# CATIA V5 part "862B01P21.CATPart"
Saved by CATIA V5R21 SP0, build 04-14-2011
Part number: 862B01P21
Bounding box of the stored display mesh (mm): x -76.5 to 76.5, y -25.54 to 25.54, z -6.5 to 6.5
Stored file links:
  C:\Users\ALI OZGUN\Desktop\alhan\862B01P21.CATPart
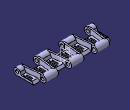
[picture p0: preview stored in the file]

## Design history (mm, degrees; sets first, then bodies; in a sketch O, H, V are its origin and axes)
Body1 (main body)
  Sketch1 on yz-plane, origin (0, 0, 0), H (0, 1, 0), V (0, 0, 1)
    construction line L1 (-19.05, 0) -> (19.05, 0)
    point P1 (-19.05, 0)
    point P2 (19.05, 0)
    line L2 (-19.05, 6.5) -> (19.05, 6.5)
    line L3 (19.05, -6.5) -> (-19.05, -6.5)
    arc A1 centre (19.05, 0) radius 6.5 from (19.05, 6.5) to (19.05, -6.5) cw
    arc A2 centre (-19.05, 0) radius 6.5 from (-19.05, -6.5) to (-19.05, 6.5) cw
    circle A3 centre (19.05, 0) radius 3.25
    circle A4 centre (-19.05, 0) radius 3.25
    distance L1 L2 = 6.5
    length L1 = 38.1
    distance P2 V = 19.05
    radius A3 = 3.25
    radius A4 = 3.25
    coincidence: P1 H
    horizontal: L1 H
    tangency: A1 L2, A2 L2, A1 L3, A2 L3
  Pad1: profile Sketch1, direction (1, 0, 0), length 76.5, mirrored extent
  Sketch2 on face of Pad1 from Sketch1.L2, origin (0, 0, 6.5), H (1, 0, 0), V (0, 1, 0)
    line L1 (38, -14) -> (64, -14)
    line L2 (64, -14) -> (64, -36.0786)
    line L3 (64, -36.0786) -> (38, -36.0786)
    line L4 (38, -36.0786) -> (38, -14)
    line L5 (-13, -14) -> (13, -14)
    line L6 (13, -14) -> (13, -36.0786)
    line L7 (13, -36.0786) -> (-13, -36.0786)
    line L8 (-13, -36.0786) -> (-13, -14)
    point P7 (13, -36.0786)
    line L9 (-64, -14) -> (-38, -14)
    line L10 (-38, -14) -> (-38, -32.269)
    line L11 (-38, -32.269) -> (-64, -32.269)
    line L12 (-64, -32.269) -> (-64, -14)
    line L13 (85.7823, 31.3847) -> (63.5, 31.3847)
    line L14 (63.5, 31.3847) -> (63.5, 14)
    line L15 (63.5, 14) -> (85.7823, 14)
    line L16 (85.7823, 14) -> (85.7823, 31.3847)
    point P17 (12.5, 31.3847)
    line L17 (12.5, 31.3847) -> (38.5, 31.3847)
    line L18 (38.5, 31.3847) -> (38.5, 14)
    line L19 (38.5, 14) -> (12.5, 14)
    line L20 (12.5, 14) -> (12.5, 31.3847)
    point P19 (38.5, 14)
    line L21 (-38.5, 32.0801) -> (-12.5, 32.0801)
    line L22 (-12.5, 32.0801) -> (-12.5, 14)
    line L23 (-12.5, 14) -> (-38.5, 14)
    line L24 (-38.5, 14) -> (-38.5, 32.0801)
    point P23 (-12.5, 14)
    line L25 (-81.4786, 33.8185) -> (-63.5, 33.8185)
    line L26 (-63.5, 33.8185) -> (-63.5, 14)
    line L27 (-63.5, 14) -> (-81.4786, 14)
    line L28 (-81.4786, 14) -> (-81.4786, 33.8185)
    point P27 (-63.5, 14)
    reference projected line E1 (76.5, 19.05) -> (76.5, -19.05) from edge [face of Pad1 from Sketch1.L2 | end face of Pad1]
    reference projected line E2 (-76.5, 19.05) -> (-76.5, -19.05) from edge [start face of Pad1 | face of Pad1 from Sketch1.L2]
    reference projected line E3 (-76.5, 19.05) -> (-76.5, -19.05) from edge [start face of Pad1 | face of Pad1 from Sketch1.L2]
    reference projected line E4 (76.5, 19.05) -> (76.5, -19.05) from edge [face of Pad1 from Sketch1.L2 | end face of Pad1]
    distance L14 E1 = 13
    distance L26 E2 = 13
    distance L12 E3 = 12.5
    distance L2 E4 = 12.5
    distance L23 L5 = 28
    distance L5 H = 14
    distance L4 L2 = 26
    distance L12 L10 = 26
    distance L10 L8 = 25
    distance L6 L4 = 25
    distance L24 L26 = 25
    distance L18 L14 = 25
    distance L26 L22 = 51
    distance L20 L18 = 26
    horizontal: L1 H, L3 H, L5 H, L7 H, L9 H, L11 H, L13 H, L15 H, L17 H, L19 H, L21 H, L23 H, L25 H, L27 H
    vertical: L2 V, L4 V, L6 V, L8 V, L10 V, L12 V, L14 V, L16 V, L18 V, L20 V, L22 V, L24 V, L26 V, L28 V
    coincidence: P7 L3, P17 L13, P19 L15, P23 L15, P27 L15, L1 L5, L9 L5
  Pocket1: profile Sketch2, direction (0, 0, -1), length 53.5
  Sketch3 on end face of Pad1, origin (76.5, 0, 0), H (0, 1, 0), V (0, 0, 1)
    projected arc E1 centre (19.05, 0) radius 6.5 from (19.05, -6.5) to (19.05, 6.5) ccw from edge [face of Pocket1 from Sketch2.L14 | face of Pad1 from Sketch1.A1]
    projected arc E2 centre (19.05, 0) radius 6.5 from (19.05, -6.5) to (13.0358, 2.4657) ccw from edge [face of Pocket1 from Sketch2.L14 | face of Pad1 from Sketch1.A1]
    point P1 (19.05, -6.5)
    projected arc E3 centre (-19.05, 0) radius 6.5 from (-19.05, 6.5) to (-19.05, -6.5) ccw from edge [face of Pad1 from Sketch1.A2 | end face of Pad1]
    projected arc E4 centre (-19.05, 0) radius 6.5 from (-13.0358, 2.4657) to (-19.05, -6.5) ccw from edge [face of Pad1 from Sketch1.A2 | end face of Pad1]
    point P4 (-19.05, -6.5)
    projected line E5 (-19.05, -6.5) -> (14, -6.5) from edge [face of Pad1 from Sketch1.L3 | end face of Pad1]
    point P5 (-19.05, -6.5)
    projected line E6 (19.05, -6.5) -> (14, -6.5) from edge [face of Pocket1 from Sketch2.L14 | face of Pad1 from Sketch1.L3]
    point P7 (19.05, -6.5)
    line L1 (-13.0358, 2.4657) -> (-11, -2.5)
    line L2 (-11, -2.5) -> (11, -2.5)
    point P10 (11, -2.5)
    line L3 (11, -2.5) -> (13.0358, 2.4657)
    distance L2 E5 = 4
    length L2 = 22
    distance P10 V = 11
    horizontal: L2 H
    tangency: L3 E1, L1 E3
    coincidence: P1 P7, P4 P5
  Pocket2: profile Sketch3, direction (-1, 0, 0), length 172.5, outer side
  Sketch4 on face of Pocket2 from Sketch3.L2, origin (0, 0, -2.5), H (1, 0, 0), V (0, 1, 0)
    projected line E1 (38, -14) -> (38, -25.55) from edge [face of Pocket2 | face of Pocket1 from Sketch2.L4]
    projected line E2 (38, -14) -> (38, -19.05) from edge [face of Pocket2 | face of Pocket1 from Sketch2.L4]
    point P1 (38, -14)
    point P2 (38, -25.55)
    projected line E3 (13, -25.55) -> (13, -14) from edge [face of Pocket2 | face of Pocket1 from Sketch2.L6]
    projected line E4 (13, -19.05) -> (13, -14) from edge [face of Pocket2 | face of Pocket1 from Sketch2.L6]
    point P3 (13, -25.55)
    point P4 (13, -14)
    projected line E5 (64, -25.55) -> (64, -14) from edge [face of Pocket2 | face of Pocket1 from Sketch2.L2]
    projected line E6 (64, -19.05) -> (64, -14) from edge [face of Pocket2 | face of Pocket1 from Sketch2.L2]
    point P5 (64, -25.55)
    point P6 (64, -14)
    projected line E7 (38.5, 14) -> (38.5, 25.55) from edge [face of Pocket2 | face of Pocket1 from Sketch2.L18]
    projected line E8 (38.5, 14) -> (38.5, 19.05) from edge [face of Pocket2 | face of Pocket1 from Sketch2.L18]
    point P7 (38.5, 14)
    point P8 (38.5, 25.55)
    projected line E9 (63.5, 14) -> (63.5, 25.55) from edge [face of Pocket1 from Sketch2.L14 | face of Pocket2]
    projected line E10 (63.5, 14) -> (63.5, 19.05) from edge [face of Pocket1 from Sketch2.L14 | face of Pocket2]
    point P9 (63.5, 14)
    point P10 (63.5, 25.55)
    projected line E11 (12.5, 25.55) -> (12.5, 14) from edge [face of Pocket2 | face of Pocket1 from Sketch2.L20]
    projected line E12 (12.5, 19.05) -> (12.5, 14) from edge [face of Pocket2 | face of Pocket1 from Sketch2.L20]
    point P11 (12.5, 25.55)
    point P12 (12.5, 14)
    offset line E13 (9.5, 25.55) -> (9.5, 14) from edge [face of Pocket2 | face of Pocket1 from Sketch2.L20]
    offset line E14 (9.5, 19.05) -> (9.5, 14) from edge [face of Pocket2 | face of Pocket1 from Sketch2.L20]
    point P13 (9.5, 25.55)
    point P14 (9.5, 14)
    offset line E15 (16, -25.55) -> (16, -14) from edge [face of Pocket2 | face of Pocket1 from Sketch2.L6]
    offset line E16 (16, -19.05) -> (16, -14) from edge [face of Pocket2 | face of Pocket1 from Sketch2.L6]
    point P15 (16, -25.55)
    point P16 (16, -14)
    offset line E17 (35, -14) -> (35, -25.55) from edge [face of Pocket2 | face of Pocket1 from Sketch2.L4]
    offset line E18 (35, -14) -> (35, -19.05) from edge [face of Pocket2 | face of Pocket1 from Sketch2.L4]
    point P17 (35, -14)
    point P18 (35, -25.55)
    offset line E19 (41.5, 14) -> (41.5, 25.55) from edge [face of Pocket2 | face of Pocket1 from Sketch2.L18]
    offset line E20 (41.5, 14) -> (41.5, 19.05) from edge [face of Pocket2 | face of Pocket1 from Sketch2.L18]
    point P19 (41.5, 14)
    point P20 (41.5, 25.55)
    offset line E21 (60.5, 14) -> (60.5, 25.55) from edge [face of Pocket1 from Sketch2.L14 | face of Pocket2]
    offset line E22 (60.5, 14) -> (60.5, 19.05) from edge [face of Pocket1 from Sketch2.L14 | face of Pocket2]
    point P21 (60.5, 14)
    point P22 (60.5, 25.55)
    offset line E23 (67, -25.55) -> (67, -14) from edge [face of Pocket2 | face of Pocket1 from Sketch2.L2]
    offset line E24 (67, -19.05) -> (67, -14) from edge [face of Pocket2 | face of Pocket1 from Sketch2.L2]
    point P23 (67, -25.55)
    point P24 (67, -14)
    line L1 (13, -14) -> (9.5, 14)
    line L2 (16, -14) -> (12.5, 14)
    line L3 (35, -14) -> (38.5, 14)
    line L4 (38, -14) -> (41.5, 14)
    line L5 (64, -14) -> (60.5, 14)
    line L6 (67, -14) -> (63.5, 14)
    projected line E25 through (0, -19.05) direction (1, 0) from axis of face of Pocket2
    projected line E26 (13, -19.05) -> (16, -19.05) from axis of face of Pocket2
    projected line E27 (64, -19.05) -> (67, -19.05) from axis of face of Pocket2
    projected line E28 (35, -19.05) -> (38, -19.05) from axis of face of Pocket2
    point P25 (-10000000, -19.05)
    point P26 (10000000, -19.05)
    point P27 (67, -19.05)
    point P28 (38, -19.05)
    point P29 (64, -19.05)
    point P30 (64, -19.05)
    point P31 (38, -19.05)
    point P32 (35, -19.05)
    point P33 (16, -19.05)
    point P34 (35, -19.05)
    point P35 (16, -19.05)
    point P36 (13, -19.05)
    point P37 (13, -19.05)
    projected line E29 through (0, 19.05) direction (1, 0) from axis of face of Pocket2
    projected line E30 (9.5, 19.05) -> (12.5, 19.05) from axis of face of Pocket2
    projected line E31 (38.5, 19.05) -> (41.5, 19.05) from axis of face of Pocket2
    projected line E32 (60.5, 19.05) -> (63.5, 19.05) from axis of face of Pocket2
    point P38 (-10000000, 19.05)
    point P39 (10000000, 19.05)
    point P40 (63.5, 19.05)
    point P41 (9.5, 19.05)
    point P42 (9.5, 19.05)
    point P43 (12.5, 19.05)
    point P44 (12.5, 19.05)
    point P45 (38.5, 19.05)
    point P46 (38.5, 19.05)
    point P47 (41.5, 19.05)
    point P48 (60.5, 19.05)
    point P49 (41.5, 19.05)
    point P50 (60.5, 19.05)
    point P51 (-10000000, -19.05)
    point P52 (10000000, -19.05)
    point P53 (-10000000, 19.05)
    point P54 (10000000, 19.05)
    construction line L7 through (0, -19.05) direction (-1, 0)
    construction line L8 through (0, 19.05) direction (-1, 0)
    point P55 (-10000000, -19.05)
    point P56 (10000000, -19.05)
    point P57 (-16, -19.05)
    point P58 (-13, -19.05)
    point P59 (-67, -19.05)
    point P60 (-64, -19.05)
    point P61 (-38, -19.05)
    point P62 (-35, -19.05)
    point P63 (-38, -25.55)
    point P64 (-38, -14)
    point P65 (-38, -19.05)
    point P66 (-13, -14)
    point P67 (-13, -25.55)
    point P68 (-13, -19.05)
    point P69 (-64, -14)
    point P70 (-64, -25.55)
    point P71 (-64, -19.05)
    point P72 (-38.5, 25.55)
    point P73 (-38.5, 14)
    point P74 (-38.5, 19.05)
    point P75 (-63.5, 25.55)
    point P76 (-63.5, 14)
    point P77 (-63.5, 19.05)
    point P78 (-12.5, 14)
    point P79 (-12.5, 25.55)
    point P80 (-12.5, 19.05)
    point P81 (-9.5, 14)
    point P82 (-9.5, 25.55)
    point P83 (-9.5, 19.05)
    point P84 (-16, -14)
    point P85 (-16, -25.55)
    point P86 (-16, -19.05)
    point P87 (-35, -25.55)
    point P88 (-35, -14)
    point P89 (-35, -19.05)
    point P90 (-41.5, 25.55)
    point P91 (-41.5, 14)
    point P92 (-41.5, 19.05)
    point P93 (-60.5, 25.55)
    point P94 (-60.5, 14)
    point P95 (-60.5, 19.05)
    point P96 (-67, -14)
    point P97 (-67, -25.55)
    line L9 (-13, -14) -> (-9.5, 14)
    line L10 (-16, -14) -> (-12.5, 14)
    line L11 (-35, -14) -> (-38.5, 14)
    line L12 (-38, -14) -> (-41.5, 14)
    line L13 (-64, -14) -> (-60.5, 14)
    line L14 (-67, -14) -> (-63.5, 14)
    point P98 (-10000000, 19.05)
    point P99 (10000000, 19.05)
    point P100 (-12.5, 19.05)
    point P101 (-9.5, 19.05)
    point P102 (-41.5, 19.05)
    point P103 (-38.5, 19.05)
    point P104 (-60.5, 19.05)
    construction line L15 through (0, -19.05) direction (-1, 0)
    line L16 (-13, -19.05) -> (-16, -19.05)
    line L17 (-64, -19.05) -> (-67, -19.05)
    line L18 (-35, -19.05) -> (-38, -19.05)
    construction line L19 (-38, -14) -> (-38, -25.55)
    line L20 (-38, -14) -> (-38, -19.05)
    construction line L21 (-13, -25.55) -> (-13, -14)
    line L22 (-13, -19.05) -> (-13, -14)
    construction line L23 (-64, -25.55) -> (-64, -14)
    line L24 (-64, -19.05) -> (-64, -14)
    construction line L25 (-38.5, 14) -> (-38.5, 25.55)
    line L26 (-38.5, 14) -> (-38.5, 19.05)
    construction line L27 (-63.5, 14) -> (-63.5, 25.55)
    line L28 (-63.5, 14) -> (-63.5, 19.05)
    construction line L29 (-12.5, 25.55) -> (-12.5, 14)
    line L30 (-12.5, 19.05) -> (-12.5, 14)
    construction line L31 (-9.5, 25.55) -> (-9.5, 14)
    line L32 (-9.5, 19.05) -> (-9.5, 14)
    construction line L33 (-16, -25.55) -> (-16, -14)
    line L34 (-16, -19.05) -> (-16, -14)
    construction line L35 (-35, -14) -> (-35, -25.55)
    line L36 (-35, -14) -> (-35, -19.05)
    construction line L37 (-41.5, 14) -> (-41.5, 25.55)
    line L38 (-41.5, 14) -> (-41.5, 19.05)
    construction line L39 (-60.5, 14) -> (-60.5, 25.55)
    line L40 (-60.5, 14) -> (-60.5, 19.05)
    construction line L41 (-67, -25.55) -> (-67, -14)
    line L42 (-67, -19.05) -> (-67, -14)
    construction line L43 through (0, 19.05) direction (-1, 0)
    line L44 (-9.5, 19.05) -> (-12.5, 19.05)
    line L45 (-38.5, 19.05) -> (-41.5, 19.05)
    line L46 (-60.5, 19.05) -> (-63.5, 19.05)
    parallelism: L2 L1, L4 L3
    coincidence: E1 P28, E5 P29, E25 P30, E25 P31, E25 P32, E15 P33, E17 P34, E25 P35, E25 P36, E3 P37, E13 P41, E29 P42, E29 P43, E11 P44, E7 P45, E29 P46, E29 P47, E29 P48, E19 P49, E21 P50, P28 P31, P29 P30, P32 P34, P33 P35, P36 P37, P41 P42, P43 P44, P45 P46, P47 P49, P48 P50
    symmetry: P26 P51 V, P25 P52 V, E25 L7 V, P39 P53 V, P38 P54 V, E29 L8 V, P26 P55 V, P25 P56 V, P33 P57 V, P37 P58 V, P27 P59 V, P29 P60 V, P28 P61 V, P34 P62 V, E25 L15 V, P2 P63 V, P1 P64 V, P31 P65 V, E1 L19 V, P4 P66 V, P3 P67 V, P36 P68 V, E3 L21 V, P6 P69 V, P5 P70 V, P30 P71 V, E5 L23 V, P8 P72 V, P7 P73 V, P46 P74 V, E7 L25 V, P10 P75 V, P9 P76 V, P40 P77 V, E9 L27 V, P12 P78 V, P11 P79 V, P43 P80 V, E11 L29 V, P14 P81 V, P13 P82 V, P42 P83 V, E13 L31 V, P16 P84 V, P15 P85 V, P35 P86 V, E15 L33 V, P18 P87 V, P17 P88 V, P32 P89 V, E17 L35 V, P20 P90 V, P19 P91 V, P47 P92 V, E19 L37 V, P22 P93 V, P21 P94 V, P48 P95 V, E21 L39 V, P24 P96 V, P23 P97 V, E23 L41 V, L1 L9 V, L2 L10 V, L3 L11 V, L4 L12 V, L5 L13 V, L6 L14 V, P39 P98 V, P38 P99 V, P44 P100 V, P41 P101 V, P49 P102 V, P45 P103 V, P50 P104 V, E29 L43 V, E25 L18 V, E25 L17 V, E25 L16 V, E1 L20 V, E3 L22 V, E5 L24 V, E7 L26 V, E9 L28 V, E11 L30 V, E13 L32 V, E15 L34 V, E17 L36 V, E19 L38 V, E21 L40 V, E23 L42 V, E29 L46 V, E29 L45 V, E29 L44 V
  Pad2: profile Sketch4, direction (0, 0, 1), length 9
  Sketch5 on yz-plane, origin (0, 0, 0), H (0, 1, 0), V (0, 0, 1)
    projected circle E1 centre (-19.05, 0) radius 3.25 from edge [end face of Pad1 | face of Pad1 from Sketch1.A4]
    circle A1 centre (19.05, 0) radius 3.25
    reference projected circle E2 centre (19.05, 0) radius 3.25 from edge [face of Pad1 from Sketch1.A3 | face of Pad2]
    coincidence: A1 E2
  Pocket3: profile Sketch5, direction (-1, 0, 0), length 95, mirrored extent
  RemoveFace1: RemoveFaces (face of Pocket2 from Sketch3.L3; face of Pocket2; face of Pocket2 from Sketch3.L3; face of Pocket2; face of Pocket2 from Sketch3.L1; face of Pocket2; face of Pocket2 from Sketch3.L1; face of Pocket2; face of Pocket2; face of Pocket2; face of Pocket2; face of Pocket2 from Sketch3.L3; face of Pocket2 from Sketch3.L3; face of Pocket2 from Sketch3.L1)
  Chamfer1: length 4, angle 45, on edge [face of Pocket1 from Sketch2.L27 | face of Pocket2 from Sketch3.L2]; edge [face of Pocket1 from Sketch2.L9 | face of Pocket2 from Sketch3.L2]; edge [face of Pocket1 from Sketch2.L19 | face of Pocket2 from Sketch3.L2]; edge [face of Pocket1 from Sketch2.L5 | face of Pocket2 from Sketch3.L2]; edge [face of Pocket1 from Sketch2.L1 | face of Pocket2 from Sketch3.L2]; edge [face of Pocket1 from Sketch2.L15 | face of Pocket2 from Sketch3.L2]; edge [face of Pocket1 from Sketch2.L23 | face of Pocket2 from Sketch3.L2]
  Body2
    Pad3: profile Sketch7, direction (0, 0, -1), length 9, mirrored extent
    TritangentFillet1: Face1 face of Pad3 from Sketch7.L36, Face2 face of Pad3 from Sketch7.L35, RemoveFace face of Pad3 from Sketch7.A31
    TritangentFillet2: Face1 face of Pad3 from Sketch7.L33, Face2 face of Pad3 from Sketch7.L34, RemoveFace face of Pad3 from Sketch7.A30
    TritangentFillet3: Face1 face of Pad3 from Sketch7.L36, Face2 face of Pad3 from Sketch7.L35, RemoveFace face of Pad3 from Sketch7.A28
    TritangentFillet4: Face1 face of Pad3 from Sketch7.L33, Face2 face of Pad3 from Sketch7.L34, RemoveFace face of Pad3 from Sketch7.A29
    TritangentFillet5: Face1 face of Pad3 from Sketch7.L24, Face2 face of Pad3 from Sketch7.L23, RemoveFace face of Pad3 from Sketch7.A21
    TritangentFillet6: Face1 face of Pad3 from Sketch7.L25, Face2 face of Pad3 from Sketch7.L26, RemoveFace face of Pad3 from Sketch7.A20
    TritangentFillet7: Face1 face of Pad3 from Sketch7.L29, Face2 face of Pad3 from Sketch7.L30, RemoveFace face of Pad3 from Sketch7.A24
    TritangentFillet8: Face1 face of Pad3 from Sketch7.L28, Face2 face of Pad3 from Sketch7.L27, RemoveFace face of Pad3 from Sketch7.A25
    TritangentFillet9: Face1 face of Pad3 from Sketch7.L24, Face2 face of Pad3 from Sketch7.L23, RemoveFace face of Pad3 from Sketch7.A22
    TritangentFillet10: Face1 face of Pad3 from Sketch7.L25, Face2 face of Pad3 from Sketch7.L26, RemoveFace face of Pad3 from Sketch7.A23
    TritangentFillet11: Face1 face of Pad3 from Sketch7.L29, Face2 face of Pad3 from Sketch7.L30, RemoveFace face of Pad3 from Sketch7.A27
    TritangentFillet12: Face1 face of Pad3 from Sketch7.L27, Face2 face of Pad3 from Sketch7.L28, RemoveFace face of Pad3 from Sketch7.A26
    TritangentFillet13: Face1 face of Pad3 from Sketch7.L13, Face2 face of Pad3 from Sketch7.L14, RemoveFace face of Pad3 from Sketch7.A14
    TritangentFillet14: Face1 face of Pad3 from Sketch7.L16, Face2 face of Pad3 from Sketch7.L15, RemoveFace face of Pad3 from Sketch7.A15
    TritangentFillet15: Face1 face of Pad3 from Sketch7.L20, Face2 face of Pad3 from Sketch7.L19, RemoveFace face of Pad3 from Sketch7.A19
    TritangentFillet16: Face1 face of Pad3 from Sketch7.L17, Face2 face of Pad3 from Sketch7.L18, RemoveFace face of Pad3 from Sketch7.A18
    TritangentFillet17: Face1 face of Pad3 from Sketch7.L13, Face2 face of Pad3 from Sketch7.L14, RemoveFace face of Pad3 from Sketch7.A13
    TritangentFillet18: Face1 face of Pad3 from Sketch7.L15, Face2 face of Pad3 from Sketch7.L16, RemoveFace face of Pad3 from Sketch7.A12
    TritangentFillet19: Face1 face of Pad3 from Sketch7.L19, Face2 face of Pad3 from Sketch7.L20, RemoveFace face of Pad3 from Sketch7.A16
    TritangentFillet20: Face1 face of Pad3 from Sketch7.L17, Face2 face of Pad3 from Sketch7.L18, RemoveFace face of Pad3 from Sketch7.A17
    TritangentFillet21: Face1 face of Pad3 from Sketch7.L1, Face2 face of Pad3 from Sketch7.L2, RemoveFace face of Pad3 from Sketch7.A5
    TritangentFillet22: Face1 face of Pad3 from Sketch7.L3, Face2 face of Pad3 from Sketch7.L4, RemoveFace face of Pad3 from Sketch7.A2
    TritangentFillet23: Face1 face of Pad3 from Sketch7.L4, Face2 face of Pad3 from Sketch7.L3, RemoveFace face of Pad3 from Sketch7.A7
    TritangentFillet24: Face1 face of Pad3 from Sketch7.L2, Face2 face of Pad3 from Sketch7.L1, RemoveFace face of Pad3 from Sketch7.A6
    Sketch6 on xy-plane, origin (0, 0, 0), H (1, 0, 0), V (0, 1, 0)
      line L1 (99.3896, -22.8416) -> (0, -22.8416)
      line L2 (0, -22.8416) -> (0, 17.017)
      line L3 (0, 17.017) -> (99.3896, 17.017)
      line L4 (99.3896, 17.017) -> (99.3896, -22.8416)
      point P3 (0, 17.017)
      horizontal: L1 H, L3 H
      vertical: L2 V, L4 V
      coincidence: P3 V
    Pocket4: profile Sketch6, direction (0, 0, -1), length 22, mirrored extent
    Mirror1: of the body so far, about yz-plane
  Remove1: tool Body2
  Sketch7 on face of Pocket2, origin (0, 0, -6.5), H (1, 0, 0), V (0, -1, 0)
    reference projected line E2 (-76.5, 19.05) -> (-76.5, -14) from edge [start face of Pad1 | face of Pocket2]
    point P3 (-76.5, 19.05)
    point P4 (-76.5, -14)
    construction circle A1 centre (-76.5, 0) radius 9
    point P5 (-76.5, 0)
    arc A2 centre (0, 0) radius 9 from (-3, -8.4853) to (-1, -8.9443) ccw
    construction circle A3 centre (-25.5, 0) radius 9
    point P6 (-25.5, 0)
    construction circle A4 centre (-51, 0) radius 9
    point P7 (-51, 0)
    line L1 (-7, 5.6569) -> (-7, -5.6569)
    line L2 (-5, 7.4833) -> (-5, -7.4833)
    line L3 (-3, 8.4853) -> (-3, -8.4853)
    line L4 (-1, 8.9443) -> (-1, -8.9443)
    point P8 (-1, 8.9443)
    point P9 (-3, 8.4853)
    point P10 (-5, 7.4833)
    point P11 (-7, 5.6569)
    point P12 (-7, -5.6569)
    point P13 (-5, -7.4833)
    point P14 (-3, -8.4853)
    point P15 (-1, -8.9443)
    arc A5 centre (0, 0) radius 9 from (-7, -5.6569) to (-5, -7.4833) ccw
    arc A6 centre (0, 0) radius 9 from (-5, 7.4833) to (-7, 5.6569) ccw
    arc A7 centre (0, 0) radius 9 from (-1, 8.9443) to (-3, 8.4853) ccw
    point P16 (1, 8.9443)
    point P17 (3, 8.4853)
    point P18 (5, 7.4833)
    point P19 (7, 5.6569)
    point P20 (7, -5.6569)
    point P21 (5, -7.4833)
    point P22 (3, -8.4853)
    point P23 (1, -8.9443)
    arc A8 centre (0, 0) radius 9 from (3, -8.4853) to (1, -8.9443) cw
    line L5 (7, 5.6569) -> (7, -5.6569)
    line L6 (5, 7.4833) -> (5, -7.4833)
    line L7 (3, 8.4853) -> (3, -8.4853)
    line L8 (1, 8.9443) -> (1, -8.9443)
    arc A9 centre (0, 0) radius 9 from (7, -5.6569) to (5, -7.4833) cw
    arc A10 centre (0, 0) radius 9 from (5, 7.4833) to (7, 5.6569) cw
    arc A11 centre (0, 0) radius 9 from (1, 8.9443) to (3, 8.4853) cw
    reference projected line E3 (-64, 14) -> (-38, 14) from edge [face of Pocket2 | face of Chamfer1]
    point P25 (-64, 14)
    point P26 (-38, 14)
    reference projected line E4 (-12.5, -14) -> (-38.5, -14) from edge [face of Pocket2 | face of Chamfer1]
    construction line L9 (-51, 14) -> (-51, -25.4597)
    point P29 (-51, 14)
    axis line L10 (-25.5, -14) -> (-25.5, 23.7094)
    point P31 (-25.5, -14)
    point P32 (-25.5, 23.7094)
    construction line L11 through (-25.5, 0) direction (1, 0)
    construction line L12 through (-25.5, 0) direction (0, 1)
    point P33 (-26.5, -8.9443)
    point P34 (-28.5, -8.4853)
    arc A12 centre (-25.5, 0) radius 9 from (-28.5, -8.4853) to (-26.5, -8.9443) ccw
    point P36 (-32.5, -5.6569)
    point P37 (-32.5, 5.6569)
    line L13 (-32.5, 5.6569) -> (-32.5, -5.6569)
    point P38 (-30.5, -7.4833)
    point P39 (-30.5, 7.4833)
    line L14 (-30.5, 7.4833) -> (-30.5, -7.4833)
    point P40 (-28.5, 8.4853)
    line L15 (-28.5, 8.4853) -> (-28.5, -8.4853)
    point P41 (-26.5, 8.9443)
    line L16 (-26.5, 8.9443) -> (-26.5, -8.9443)
    arc A13 centre (-25.5, 0) radius 9 from (-32.5, -5.6569) to (-30.5, -7.4833) ccw
    arc A14 centre (-25.5, 0) radius 9 from (-30.5, 7.4833) to (-32.5, 5.6569) ccw
    arc A15 centre (-25.5, 0) radius 9 from (-26.5, 8.9443) to (-28.5, 8.4853) ccw
    point P42 (-24.5, -8.9443)
    point P43 (-22.5, -8.4853)
    arc A16 centre (-25.5, 0) radius 9 from (-22.5, -8.4853) to (-24.5, -8.9443) cw
    point P45 (-18.5, -5.6569)
    point P46 (-18.5, 5.6569)
    line L17 (-18.5, 5.6569) -> (-18.5, -5.6569)
    point P47 (-20.5, -7.4833)
    point P48 (-20.5, 7.4833)
    line L18 (-20.5, 7.4833) -> (-20.5, -7.4833)
    point P49 (-22.5, 8.4853)
    line L19 (-22.5, 8.4853) -> (-22.5, -8.4853)
    point P50 (-24.5, 8.9443)
    line L20 (-24.5, 8.9443) -> (-24.5, -8.9443)
    arc A17 centre (-25.5, 0) radius 9 from (-18.5, -5.6569) to (-20.5, -7.4833) cw
    arc A18 centre (-25.5, 0) radius 9 from (-20.5, 7.4833) to (-18.5, 5.6569) cw
    arc A19 centre (-25.5, 0) radius 9 from (-24.5, 8.9443) to (-22.5, 8.4853) cw
    construction line L21 through (-51, 0) direction (1, 0)
    construction line L22 through (-51, 0) direction (0, 1)
    point P51 (-52, -8.9443)
    point P52 (-54, -8.4853)
    arc A20 centre (-51, 0) radius 9 from (-54, -8.4853) to (-52, -8.9443) ccw
    point P54 (-58, -5.6569)
    point P55 (-58, 5.6569)
    line L23 (-58, 5.6569) -> (-58, -5.6569)
    point P56 (-56, -7.4833)
    point P57 (-56, 7.4833)
    line L24 (-56, 7.4833) -> (-56, -7.4833)
    point P58 (-54, 8.4853)
    line L25 (-54, 8.4853) -> (-54, -8.4853)
    point P59 (-52, 8.9443)
    line L26 (-52, 8.9443) -> (-52, -8.9443)
    arc A21 centre (-51, 0) radius 9 from (-58, -5.6569) to (-56, -7.4833) ccw
    arc A22 centre (-51, 0) radius 9 from (-56, 7.4833) to (-58, 5.6569) ccw
    arc A23 centre (-51, 0) radius 9 from (-52, 8.9443) to (-54, 8.4853) ccw
    point P60 (-50, -8.9443)
    point P61 (-48, -8.4853)
    arc A24 centre (-51, 0) radius 9 from (-48, -8.4853) to (-50, -8.9443) cw
    point P63 (-44, -5.6569)
    point P64 (-44, 5.6569)
    line L27 (-44, 5.6569) -> (-44, -5.6569)
    point P65 (-46, -7.4833)
    point P66 (-46, 7.4833)
    line L28 (-46, 7.4833) -> (-46, -7.4833)
    point P67 (-48, 8.4853)
    line L29 (-48, 8.4853) -> (-48, -8.4853)
    point P68 (-50, 8.9443)
    line L30 (-50, 8.9443) -> (-50, -8.9443)
    arc A25 centre (-51, 0) radius 9 from (-44, -5.6569) to (-46, -7.4833) cw
    arc A26 centre (-51, 0) radius 9 from (-46, 7.4833) to (-44, 5.6569) cw
    arc A27 centre (-51, 0) radius 9 from (-50, 8.9443) to (-48, 8.4853) cw
    construction line L31 through (-76.5, 0) direction (1, 0)
    construction line L32 through (-76.5, 0) direction (0, 1)
    point P69 (-75.5, -8.9443)
    point P70 (-73.5, -8.4853)
    arc A28 centre (-76.5, 0) radius 9 from (-73.5, -8.4853) to (-75.5, -8.9443) cw
    point P72 (-69.5, -5.6569)
    point P73 (-69.5, 5.6569)
    line L33 (-69.5, 5.6569) -> (-69.5, -5.6569)
    point P74 (-71.5, -7.4833)
    point P75 (-71.5, 7.4833)
    line L34 (-71.5, 7.4833) -> (-71.5, -7.4833)
    point P76 (-73.5, 8.4853)
    line L35 (-73.5, 8.4853) -> (-73.5, -8.4853)
    point P77 (-75.5, 8.9443)
    line L36 (-75.5, 8.9443) -> (-75.5, -8.9443)
    arc A29 centre (-76.5, 0) radius 9 from (-69.5, -5.6569) to (-71.5, -7.4833) cw
    arc A30 centre (-76.5, 0) radius 9 from (-71.5, 7.4833) to (-69.5, 5.6569) cw
    arc A31 centre (-76.5, 0) radius 9 from (-75.5, 8.9443) to (-73.5, 8.4853) cw
    point P78 (76.5, -14)
    point P79 (76.5, 19.05)
    construction circle A32 centre (76.5, 0) radius 9
    construction circle A33 centre (25.5, 0) radius 9
    construction circle A34 centre (51, 0) radius 9
    point P83 (38, 14)
    point P84 (64, 14)
    point P85 (25.5, 23.7094)
    point P86 (25.5, -14)
    construction line L37 (25.5, -14) -> (25.5, 23.7094)
    point P87 (26.5, -8.9443)
    point P88 (28.5, -8.4853)
    arc A35 centre (25.5, 0) radius 9 from (28.5, -8.4853) to (26.5, -8.9443) cw
    point P90 (32.5, -5.6569)
    point P91 (32.5, 5.6569)
    line L38 (32.5, 5.6569) -> (32.5, -5.6569)
    point P92 (30.5, -7.4833)
    point P93 (30.5, 7.4833)
    line L39 (30.5, 7.4833) -> (30.5, -7.4833)
    point P94 (28.5, 8.4853)
    line L40 (28.5, 8.4853) -> (28.5, -8.4853)
    point P95 (26.5, 8.9443)
    line L41 (26.5, 8.9443) -> (26.5, -8.9443)
    arc A36 centre (25.5, 0) radius 9 from (32.5, -5.6569) to (30.5, -7.4833) cw
    arc A37 centre (25.5, 0) radius 9 from (30.5, 7.4833) to (32.5, 5.6569) cw
    arc A38 centre (25.5, 0) radius 9 from (26.5, 8.9443) to (28.5, 8.4853) cw
    point P96 (24.5, -8.9443)
    point P97 (22.5, -8.4853)
    arc A39 centre (25.5, 0) radius 9 from (22.5, -8.4853) to (24.5, -8.9443) ccw
    point P99 (18.5, -5.6569)
    point P100 (18.5, 5.6569)
    line L42 (18.5, 5.6569) -> (18.5, -5.6569)
    point P101 (20.5, -7.4833)
    point P102 (20.5, 7.4833)
    line L43 (20.5, 7.4833) -> (20.5, -7.4833)
    point P103 (22.5, 8.4853)
    line L44 (22.5, 8.4853) -> (22.5, -8.4853)
    point P104 (24.5, 8.9443)
    line L45 (24.5, 8.9443) -> (24.5, -8.9443)
    arc A40 centre (25.5, 0) radius 9 from (18.5, -5.6569) to (20.5, -7.4833) ccw
    arc A41 centre (25.5, 0) radius 9 from (20.5, 7.4833) to (18.5, 5.6569) ccw
    arc A42 centre (25.5, 0) radius 9 from (24.5, 8.9443) to (22.5, 8.4853) ccw
    point P105 (52, -8.9443)
    point P106 (54, -8.4853)
    arc A43 centre (51, 0) radius 9 from (54, -8.4853) to (52, -8.9443) cw
    point P108 (58, -5.6569)
    point P109 (58, 5.6569)
    line L46 (58, 5.6569) -> (58, -5.6569)
    point P110 (56, -7.4833)
    point P111 (56, 7.4833)
    line L47 (56, 7.4833) -> (56, -7.4833)
    point P112 (54, 8.4853)
    line L48 (54, 8.4853) -> (54, -8.4853)
    point P113 (52, 8.9443)
    line L49 (52, 8.9443) -> (52, -8.9443)
    arc A44 centre (51, 0) radius 9 from (58, -5.6569) to (56, -7.4833) cw
    arc A45 centre (51, 0) radius 9 from (56, 7.4833) to (58, 5.6569) cw
    arc A46 centre (51, 0) radius 9 from (52, 8.9443) to (54, 8.4853) cw
    point P114 (50, -8.9443)
    point P115 (48, -8.4853)
    arc A47 centre (51, 0) radius 9 from (48, -8.4853) to (50, -8.9443) ccw
    point P117 (44, -5.6569)
    point P118 (44, 5.6569)
    line L50 (44, 5.6569) -> (44, -5.6569)
    point P119 (46, -7.4833)
    point P120 (46, 7.4833)
    line L51 (46, 7.4833) -> (46, -7.4833)
    point P121 (48, 8.4853)
    line L52 (48, 8.4853) -> (48, -8.4853)
    point P122 (50, 8.9443)
    line L53 (50, 8.9443) -> (50, -8.9443)
    arc A48 centre (51, 0) radius 9 from (44, -5.6569) to (46, -7.4833) ccw
    arc A49 centre (51, 0) radius 9 from (46, 7.4833) to (44, 5.6569) ccw
    arc A50 centre (51, 0) radius 9 from (50, 8.9443) to (48, 8.4853) ccw
    point P123 (75.5, -8.9443)
    point P124 (73.5, -8.4853)
    arc A51 centre (76.5, 0) radius 9 from (73.5, -8.4853) to (75.5, -8.9443) ccw
    point P126 (69.5, -5.6569)
    point P127 (69.5, 5.6569)
    line L54 (69.5, 5.6569) -> (69.5, -5.6569)
    point P128 (71.5, -7.4833)
    point P129 (71.5, 7.4833)
    line L55 (71.5, 7.4833) -> (71.5, -7.4833)
    point P130 (73.5, 8.4853)
    line L56 (73.5, 8.4853) -> (73.5, -8.4853)
    point P131 (75.5, 8.9443)
    line L57 (75.5, 8.9443) -> (75.5, -8.9443)
    arc A52 centre (76.5, 0) radius 9 from (69.5, -5.6569) to (71.5, -7.4833) ccw
    arc A53 centre (76.5, 0) radius 9 from (71.5, 7.4833) to (69.5, 5.6569) ccw
    arc A54 centre (76.5, 0) radius 9 from (75.5, 8.9443) to (73.5, 8.4853) ccw
    construction line L58 (76.5, 19.05) -> (76.5, -14)
    construction line L59 (64, 14) -> (38, 14)
    radius A2 = 9
    distance L4 L3 = 2
    distance L2 L1 = 2
    distance L4 V = 1
    distance L3 L2 = 2
    radius A3 = 9
    radius A4 = 9
    radius A1 = 9
    coincidence: P5 E2, P5 H, P6 H, P7 H, A2 P8, A2 P10, A2 P12, A2 A5, A2 A6, A2 A7, P6 L10, P7 L9
    vertical: L1 V, L2 V, L3 V, L4 V, L9 V, L10 V
    symmetry: P8 P16 V, P9 P17 V, P10 P18 V, P11 P19 V, P12 P20 V, P13 P21 V, P14 P22 V, P15 P23 V, A2 A8 V, L1 L5 V, L2 L6 V, L3 L7 V, L4 L8 V, A5 A9 V, A6 A10 V, A7 A11 V, P4 P78 V, P3 P79 V, E2 L58 V, A1 A32 V, A3 A33 V, A4 A34 V, P26 P83 V, P25 P84 V, E3 L59 V, P32 P85 V, P31 P86 V, L10 L37 V, P33 P87 V, P34 P88 V, A12 A35 V, P36 P90 V, P37 P91 V, L13 L38 V, P38 P92 V, P39 P93 V, L14 L39 V, P40 P94 V, L15 L40 V, P41 P95 V, L16 L41 V, A13 A36 V, A14 A37 V, A15 A38 V, P42 P96 V, P43 P97 V, A16 A39 V, P45 P99 V, P46 P100 V, L17 L42 V, P47 P101 V, P48 P102 V, L18 L43 V, P49 P103 V, L19 L44 V, P50 P104 V, L20 L45 V, A17 A40 V, A18 A41 V, A19 A42 V, P51 P105 V, P52 P106 V, A20 A43 V, P54 P108 V, P55 P109 V, L23 L46 V, P56 P110 V, P57 P111 V, L24 L47 V, P58 P112 V, L25 L48 V, P59 P113 V, L26 L49 V, A21 A44 V, A22 A45 V, A23 A46 V, P60 P114 V, P61 P115 V, A24 A47 V, P63 P117 V, P64 P118 V, L27 L50 V, P65 P119 V, P66 P120 V, L28 L51 V, P67 P121 V, L29 L52 V, P68 P122 V, L30 L53 V, A25 A48 V, A26 A49 V, A27 A50 V, P69 P123 V, P70 P124 V, A28 A51 V, P72 P126 V, P73 P127 V, L33 L54 V, P74 P128 V, P75 P129 V, L34 L55 V, P76 P130 V, L35 L56 V, P77 P131 V, L36 L57 V, A29 A52 V, A30 A53 V, A31 A54 V
    midpoint: P29 E3, P31 E4
Body3
  Solid1: linked copy from another document
  Translate1: Direction zx-plane, Length 38.1, ToTransfor Solid1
